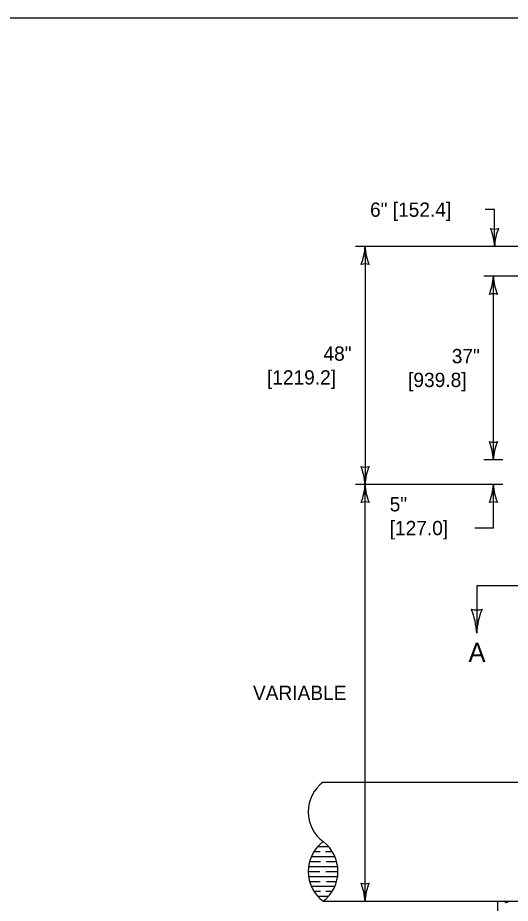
# Model space of a CAD drawing. Extents: x 49991.4 to 50028.3, y 49987.6 to 50011.4.
# Drawn here: x 50005.208 to 50007.274, y 49995.28 to 49998.999 of the extents above; entities that cross this region are included whole.
import ezdxf

# ---------------------------------------------------------------- set-up
doc = ezdxf.new("R2010")
doc.units = 0
for name, color, linetype in [('Level 1', 7, 'Continuous'), ('Level 2', 7, 'Continuous'), ('Level 3', 7, 'Continuous'), ('Level 6', 7, 'Continuous')]:
    doc.layers.add(name, color=color, linetype=linetype)

msp = doc.modelspace()

# ---------------------------------------------------------------- linework, layer by layer
at = {"layer": 'Level 1'}
for p, q in [((50006.4889, 49995.7888), (50007.3877, 49995.7888)), ((50006.4504, 49995.4971), (50006.4765, 49995.4971)), ((50006.4661, 49995.518), (50006.5115, 49995.518)), ((50006.499, 49995.4971), (50006.5273, 49995.4971)), ((50006.432, 49995.4554), (50006.4776, 49995.4554)), ((50006.4394, 49995.4763), (50006.5383, 49995.4763)), ((50006.5022, 49995.4554), (50006.5457, 49995.4554)), ((50006.4277, 49995.4346), (50006.5499, 49995.4346)), ((50006.4263, 49995.4138), (50006.4755, 49995.4138)), ((50006.4277, 49995.393), (50006.5499, 49995.393)), ((50006.5001, 49995.4138), (50006.5513, 49995.4138)), ((50006.432, 49995.3721), (50006.4765, 49995.3721)), ((50006.4394, 49995.3513), (50006.5383, 49995.3513)), ((50006.5033, 49995.3721), (50006.5457, 49995.3721)), ((50006.4504, 49995.3304), (50006.4787, 49995.3304)), ((50006.4661, 49995.3096), (50006.5115, 49995.3096)), ((50006.5011, 49995.3304), (50006.5273, 49995.3304)), ((50006.4889, 49995.2888), (50008.888, 49995.2888)), ((50007.221, 49995.2888), (50007.221, 49995.1638))]:
    msp.add_line(p, q, dxfattribs=at)
msp.add_lwpolyline([(49999.3835, 49998.9992), (50016.7501, 49998.9992), (50016.7501, 49987.7988), (49999.3835, 49987.7988)], close=True, dxfattribs=at)
for points in [[(50007.2545, 49995.2818), (50007.2578, 49995.2888)], [(50007.2604, 49995.2888), (50007.2652, 49995.2852), (50007.2545, 49995.2818)]]:
    msp.add_lwpolyline(points, dxfattribs=at)
for centre, start, end in [((50006.5826, 49995.6638), 126.8699, 233.1301), ((50006.5826, 49995.4138), 126.8699, 233.1301), ((50006.3951, 49995.4138), 306.8699, 53.1301)]:
    msp.add_arc(centre, 0.1563, start, end, dxfattribs=at)
at = {"layer": 'Level 3'}
for p, q in [((50007.2084, 49998.1931), (50007.1684, 49998.1931)), ((50007.2084, 49998.0383), (50007.2084, 49998.1931)), ((50007.4938, 49998.0383), (50006.6251, 49998.0383)), ((50006.6651, 49998.0383), (50006.6651, 49997.0388)), ((50007.4938, 49997.9133), (50007.1635, 49997.9133)), ((50007.2035, 49997.143), (50007.2035, 49997.9133)), ((50007.2435, 49997.143), (50007.1635, 49997.143)), ((50007.2435, 49997.0388), (50006.6251, 49997.0388)), ((50006.6651, 49995.2888), (50006.6651, 49997.0388)), ((50007.2035, 49996.8559), (50007.2035, 49997.0388)), ((50007.2035, 49996.8559), (50007.1262, 49996.8559))]:
    msp.add_line(p, q, dxfattribs=at)
for centre, radius, start, end in [((50007.2084, 49998.1665), 0.0548, 252.1388, 287.8612), ((50006.9757, 49998.0268), 0.233, 2.8273, 22.0772), ((50007.4305, 49998.0292), 0.2223, 157.456, 177.6395), ((50006.443, 49998.0475), 0.2223, 337.456, 357.6395), ((50006.8978, 49998.0498), 0.233, 182.8273, 202.0772), ((50006.6651, 49997.9101), 0.0548, 72.1388, 107.8612), ((50006.9814, 49997.9225), 0.2223, 337.456, 357.6395), ((50007.4362, 49997.9248), 0.233, 182.8273, 202.0772), ((50007.2035, 49997.7851), 0.0548, 72.1388, 107.8612), ((50007.2035, 49997.2712), 0.0548, 252.1388, 287.8612), ((50006.9708, 49997.1315), 0.233, 2.8273, 22.0772), ((50007.4256, 49997.1339), 0.2223, 157.456, 177.6395), ((50006.6651, 49997.167), 0.0548, 252.1388, 287.8612), ((50006.4324, 49997.0273), 0.233, 2.8273, 22.0772), ((50006.8872, 49997.0297), 0.2223, 157.456, 177.6395), ((50006.443, 49997.048), 0.2223, 337.456, 357.6395), ((50006.8978, 49997.0503), 0.233, 182.8273, 202.0772), ((50006.9814, 49997.048), 0.2223, 337.456, 357.6395), ((50007.4362, 49997.0503), 0.233, 182.8273, 202.0772), ((50006.6651, 49996.9106), 0.0548, 72.1388, 107.8612), ((50007.2035, 49996.9106), 0.0548, 72.1388, 107.8612), ((50007.1335, 49996.5848), 0.073, 252.1388, 287.8612), ((50006.8232, 49996.3985), 0.3107, 2.8273, 22.0772), ((50007.4297, 49996.4016), 0.2964, 157.456, 177.6395), ((50006.6651, 49995.417), 0.0548, 252.1388, 287.8612), ((50006.4324, 49995.2773), 0.233, 2.8273, 22.0772), ((50006.8872, 49995.2797), 0.2223, 157.456, 177.6395)]:
    msp.add_arc(centre, radius, start, end, dxfattribs=at)
at = {"layer": 'Level 6'}
for p, q in [((50007.1335, 49996.6138), (50007.1335, 49996.4138)), ((50007.463, 49996.6138), (50007.1335, 49996.6138))]:
    msp.add_line(p, q, dxfattribs=at)

# ---------------------------------------------------------------- texts
at = {"layer": 'Level 2'}
for s, height, p in [('6" [152.4]', 0.06, (50006.6859, 49998.1631)), ('48"', 0.06, (50006.4905, 49997.5585)), ('37"', 0.06, (50007.0289, 49997.5481)), ('[1219.2]', 0.06, (50006.2533, 49997.4585)), ('[939.8]', 0.06, (50006.8456, 49997.4481)), ('5"', 0.06, (50006.7683, 49996.9259)), ('[127.0]', 0.06, (50006.7683, 49996.8259)), ('A', 0.0799, (50007.0992, 49996.2939)), ('VARIABLE', 0.06, (50006.1946, 49996.1338))]:
    msp.add_text(s, height=height, dxfattribs=at).set_placement(p)

doc.saveas('drawing.dxf')
